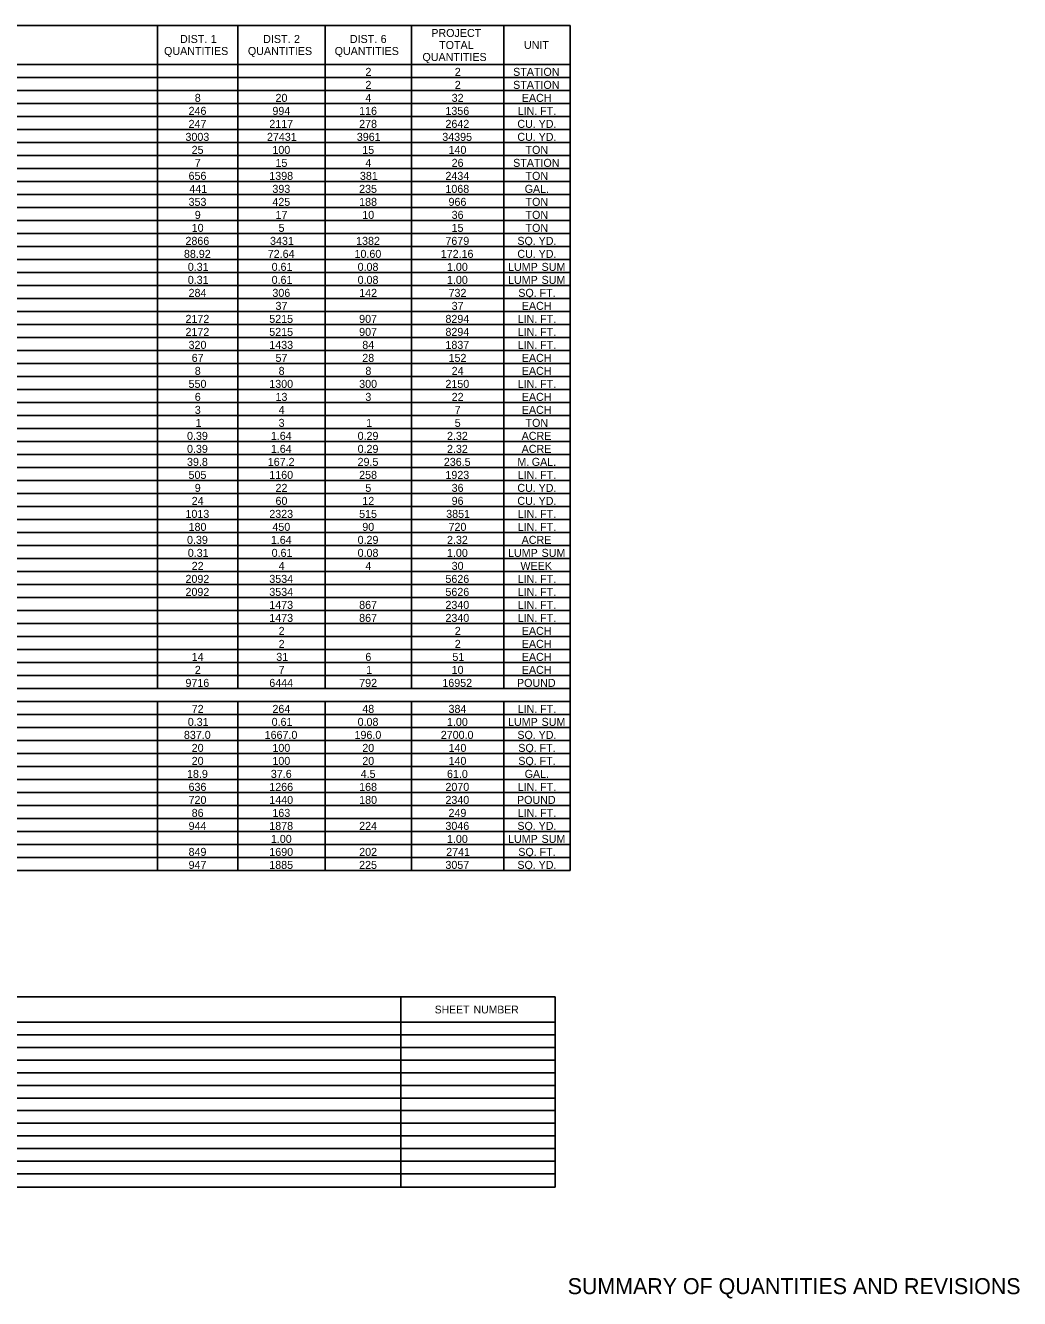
# Model space of a CAD drawing. Extents: x 542596 to 1930787, y -1948294 to 596640.
# Drawn here: x 545014 to 545760, y -1948294 to -1947339 of the extents above; entities that cross this region are included whole.
import ezdxf

# ---------------------------------------------------------------- set-up
doc = ezdxf.new("R2010")
doc.units = 0
doc.layers.add('Default', color=7, linetype='Continuous')
doc.layers.add('R_Border', color=7, linetype='Continuous')

msp = doc.modelspace()

# ---------------------------------------------------------------- linework, layer by layer
at = {"layer": 'Default'}
for p, q in [((544543.96, -1947339.48), (545422.43, -1947339.48)), ((545112.87, -1947836.73), (545112.87, -1947339.48)), ((545112.87, -1947700.23), (545112.87, -1947339.48)), ((545173.32, -1947836.73), (545173.32, -1947339.48)), ((545173.32, -1947368.73), (545173.32, -1947339.48)), ((545238.65, -1947836.73), (545238.65, -1947339.48)), ((545238.65, -1947368.73), (545238.65, -1947339.48)), ((545303.48, -1947836.73), (545303.48, -1947339.48)), ((545372.71, -1947836.73), (545372.71, -1947339.48)), ((545372.71, -1947836.73), (545372.71, -1947339.48)), ((545422.43, -1947973.23), (545422.43, -1947339.48)), ((544543.96, -1947368.73), (545422.43, -1947368.73)), ((544543.96, -1947378.48), (545422.43, -1947378.48)), ((544543.96, -1947388.23), (545422.43, -1947388.23)), ((544543.96, -1947397.98), (545422.43, -1947397.98)), ((544543.96, -1947407.73), (545422.43, -1947407.73)), ((544543.96, -1947417.48), (545422.43, -1947417.48)), ((544543.96, -1947427.23), (545422.43, -1947427.23)), ((544543.96, -1947436.98), (545422.43, -1947436.98)), ((544543.96, -1947446.73), (545422.43, -1947446.73)), ((544543.96, -1947456.48), (545422.43, -1947456.48)), ((544543.96, -1947466.23), (545422.43, -1947466.23)), ((544543.96, -1947475.98), (545422.43, -1947475.98)), ((544543.96, -1947485.73), (545422.43, -1947485.73)), ((544543.96, -1947495.48), (545422.43, -1947495.48)), ((544543.96, -1947505.23), (545422.43, -1947505.23)), ((544543.96, -1947514.98), (545422.43, -1947514.98)), ((544543.96, -1947524.73), (545422.43, -1947524.73)), ((544543.96, -1947534.48), (545422.43, -1947534.48)), ((544543.96, -1947544.23), (545422.43, -1947544.23)), ((544543.96, -1947553.98), (545422.43, -1947553.98)), ((544543.96, -1947563.73), (545422.43, -1947563.73)), ((544543.96, -1947573.48), (545422.43, -1947573.48)), ((544543.96, -1947583.23), (545422.43, -1947583.23)), ((544543.96, -1947592.98), (545422.43, -1947592.98)), ((544543.96, -1947602.73), (545422.43, -1947602.73)), ((544543.96, -1947612.48), (545422.43, -1947612.48)), ((544543.96, -1947622.23), (545422.43, -1947622.23)), ((544543.96, -1947631.98), (545422.43, -1947631.98)), ((544543.96, -1947641.73), (545422.43, -1947641.73)), ((544543.96, -1947651.48), (545422.43, -1947651.48)), ((544543.96, -1947661.23), (545422.43, -1947661.23)), ((544543.96, -1947670.98), (545422.43, -1947670.98)), ((544543.96, -1947680.73), (545422.43, -1947680.73)), ((544543.96, -1947690.48), (545422.43, -1947690.48)), ((544543.96, -1947700.23), (545422.43, -1947700.23)), ((544543.96, -1947709.98), (545422.43, -1947709.98)), ((545112.87, -1947836.73), (545112.87, -1947709.98)), ((545372.71, -1947709.98), (545422.43, -1947709.98)), ((544543.96, -1947719.73), (545422.43, -1947719.73)), ((544543.96, -1947729.48), (545422.43, -1947729.48)), ((544543.96, -1947739.23), (545422.43, -1947739.23)), ((544543.96, -1947748.98), (545422.43, -1947748.98)), ((545026.1, -1947748.98), (545112.87, -1947748.98)), ((545112.87, -1947748.98), (545422.43, -1947748.98)), ((544543.96, -1947758.73), (545422.43, -1947758.73)), ((544543.96, -1947768.48), (545422.43, -1947768.48)), ((544543.96, -1947778.23), (545422.43, -1947778.23)), ((544543.96, -1947787.98), (545422.43, -1947787.98)), ((544543.96, -1947797.73), (545422.43, -1947797.73)), ((544543.96, -1947807.48), (545422.43, -1947807.48)), ((544543.96, -1947817.23), (545422.43, -1947817.23)), ((544543.96, -1947826.98), (545422.43, -1947826.98)), ((544543.96, -1947836.73), (545422.43, -1947836.73)), ((544543.96, -1947836.73), (545422.43, -1947836.73)), ((544543.96, -1947846.48), (545422.43, -1947846.48)), ((544543.96, -1947846.48), (545422.43, -1947846.48)), ((545112.87, -1947973.23), (545112.87, -1947846.48)), ((545112.87, -1947973.23), (545112.87, -1947846.48)), ((545173.32, -1947973.23), (545173.32, -1947846.48)), ((545238.65, -1947973.23), (545238.65, -1947846.48)), ((545238.65, -1947973.23), (545238.65, -1947846.48)), ((545303.48, -1947973.23), (545303.48, -1947846.48)), ((545303.48, -1947973.23), (545303.48, -1947846.48)), ((545372.71, -1947973.23), (545372.71, -1947846.48)), ((545372.71, -1947973.23), (545372.71, -1947846.48)), ((544543.96, -1947856.23), (545422.43, -1947856.23)), ((544543.96, -1947865.98), (545422.43, -1947865.98)), ((544543.96, -1947875.73), (545422.43, -1947875.73)), ((544543.96, -1947885.48), (545422.43, -1947885.48)), ((544543.96, -1947895.23), (545422.43, -1947895.23)), ((545026.1, -1947895.23), (545112.87, -1947895.23)), ((545112.87, -1947895.23), (545238.65, -1947895.23)), ((545238.65, -1947895.23), (545372.71, -1947895.23)), ((545372.71, -1947895.23), (545422.43, -1947895.23)), ((544543.96, -1947904.98), (545422.43, -1947904.98)), ((544543.96, -1947914.73), (545422.43, -1947914.73)), ((544543.96, -1947924.48), (545422.43, -1947924.48)), ((544543.96, -1947934.23), (545422.43, -1947934.23)), ((544543.96, -1947943.98), (545422.43, -1947943.98)), ((545026.1, -1947943.98), (545112.87, -1947943.98)), ((545112.87, -1947943.98), (545238.65, -1947943.98)), ((545238.65, -1947943.98), (545372.71, -1947943.98)), ((545372.71, -1947943.98), (545422.43, -1947943.98)), ((544543.96, -1947953.73), (545422.43, -1947953.73)), ((544543.96, -1947963.48), (545422.43, -1947963.48)), ((544543.96, -1947973.23), (545422.43, -1947973.23)), ((544556.08, -1948068.01), (545411.29, -1948068.01)), ((545110.26, -1948068.01), (545411.29, -1948068.01)), ((545295.62, -1948086.97), (545295.62, -1948068.01)), ((545295.62, -1948210.7), (545295.62, -1948068.01)), ((545411.29, -1948210.7), (545411.29, -1948068.01)), ((544556.08, -1948086.97), (545411.29, -1948086.97)), ((545295.62, -1948086.97), (545411.29, -1948086.97)), ((544556.08, -1948096.45), (545411.29, -1948096.45)), ((544556.08, -1948105.93), (545411.29, -1948105.93)), ((544556.08, -1948115.42), (545411.29, -1948115.42)), ((544556.08, -1948124.9), (545411.29, -1948124.9)), ((544556.08, -1948134.38), (545411.29, -1948134.38)), ((544556.08, -1948143.86), (545411.29, -1948143.86)), ((544556.08, -1948153.34), (545411.29, -1948153.34)), ((544556.08, -1948162.82), (545411.29, -1948162.82)), ((544556.08, -1948172.3), (545411.29, -1948172.3)), ((544556.08, -1948181.78), (545411.29, -1948181.78)), ((544556.08, -1948191.27), (545411.29, -1948191.27)), ((544556.08, -1948200.75), (545411.29, -1948200.75)), ((544556.08, -1948210.7), (545411.29, -1948210.7))]:
    msp.add_line(p, q, dxfattribs=at)

# ---------------------------------------------------------------- texts
for s, height, p in [('PROJECT', 6, (545318.38, -1947348.11)), ('DIST.', 6, (545129.86, -1947352.61)), (' 1', 6, (545150.71, -1947352.61)), ('DIST.', 6, (545192.27, -1947352.61)), (' 2', 6, (545213.12, -1947352.61)), ('DIST.', 6, (545257.29, -1947352.61)), (' 6', 6, (545278.14, -1947352.61)), ('TOTAL', 6, (545324.25, -1947357.11)), ('UNIT', 6, (545387.88, -1947357.11)), ('QUANTITIES', 6, (545117.92, -1947361.61)), ('QUANTITIES', 6, (545180.8, -1947361.61)), ('QUANTITIES', 6, (545245.88, -1947361.61)), ('QUANTITIES', 6, (545311.75, -1947366.11)), ('2', 6, (545268.96, -1947377.28)), ('2', 6, (545335.99, -1947377.28)), ('STATION', 6, (545379.75, -1947377.28)), ('2', 6, (545268.96, -1947387.03)), ('2', 6, (545335.99, -1947387.03)), ('STATION', 6, (545379.75, -1947387.03)), ('8', 6, (545140.95, -1947396.78)), ('20', 6, (545201.52, -1947396.78)), ('4', 6, (545268.94, -1947396.78)), ('32', 6, (545333.66, -1947396.78)), ('EACH', 6, (545386.26, -1947396.78)), ('246', 6, (545136.3, -1947406.53)), ('994', 6, (545199.2, -1947406.53)), ('116', 6, (545264.26, -1947406.53)), ('1356', 6, (545328.97, -1947406.53)), ('LIN.', 6, (545383.17, -1947406.53)), (' FT.', 6, (545397.81, -1947406.53)), ('247', 6, (545136.3, -1947416.28)), ('2117', 6, (545196.85, -1947416.28)), ('278', 6, (545264.26, -1947416.28)), ('2642', 6, (545329, -1947416.28)), ('CU.', 6, (545382.93, -1947416.28)), (' YD.', 6, (545396.64, -1947416.28)), ('3003', 6, (545133.97, -1947426.03)), ('27431', 6, (545195.1, -1947426.03)), ('3961', 6, (545262.51, -1947426.03)), ('34395', 6, (545326.61, -1947426.03)), ('CU.', 6, (545382.93, -1947426.03)), (' YD.', 6, (545396.64, -1947426.03)), ('25', 6, (545138.6, -1947435.78)), ('100', 6, (545199.19, -1947435.78)), ('15', 6, (545266.57, -1947435.78)), ('140', 6, (545331.31, -1947435.78)), ('TON', 6, (545389.06, -1947435.78)), ('7', 6, (545140.96, -1947445.53)), ('15', 6, (545201.49, -1947445.53)), ('4', 6, (545268.94, -1947445.53)), ('26', 6, (545333.63, -1947445.53)), ('STATION', 6, (545379.75, -1947445.53)), ('656', 6, (545136.3, -1947455.28)), ('1398', 6, (545196.85, -1947455.28)), ('381', 6, (545264.84, -1947455.28)), ('2434', 6, (545328.98, -1947455.28)), ('TON', 6, (545389.06, -1947455.28)), ('441', 6, (545136.88, -1947465.03)), ('393', 6, (545199.18, -1947465.03)), ('235', 6, (545264.24, -1947465.03)), ('1068', 6, (545328.96, -1947465.03)), ('GAL.', 6, (545388.39, -1947465.03)), ('353', 6, (545136.3, -1947474.78)), ('425', 6, (545199.16, -1947474.78)), ('188', 6, (545264.26, -1947474.78)), ('966', 6, (545331.3, -1947474.78)), ('TON', 6, (545389.06, -1947474.78)), ('9', 6, (545140.95, -1947484.53)), ('17', 6, (545201.51, -1947484.53)), ('10', 6, (545266.61, -1947484.53)), ('36', 6, (545333.63, -1947484.53)), ('TON', 6, (545389.06, -1947484.53)), ('10', 6, (545138.64, -1947494.28)), ('5', 6, (545203.82, -1947494.28)), ('15', 6, (545333.6, -1947494.28)), ('TON', 6, (545389.06, -1947494.28)), ('2866', 6, (545133.97, -1947504.03)), ('3431', 6, (545197.43, -1947504.03)), ('1382', 6, (545261.97, -1947504.03)), ('7679', 6, (545328.96, -1947504.03)), ('SQ.', 6, (545382.93, -1947504.03)), (' YD.', 6, (545396.64, -1947504.03)), ('88.92', 6, (545132.83, -1947513.78)), ('72.64', 6, (545195.7, -1947513.78)), ('10.60', 6, (545260.78, -1947513.78)), ('172.16', 6, (545325.47, -1947513.78)), ('CU.', 6, (545382.93, -1947513.78)), (' YD.', 6, (545396.64, -1947513.78)), ('0.31', 6, (545135.71, -1947523.53)), ('0.61', 6, (545198.6, -1947523.53)), ('0.08', 6, (545263.1, -1947523.53)), ('1.00', 6, (545330.14, -1947523.53)), ('LUMP', 6, (545375.94, -1947523.53)), (' SUM', 6, (545398.87, -1947523.53)), ('0.31', 6, (545135.71, -1947533.28)), ('0.61', 6, (545198.6, -1947533.28)), ('0.08', 6, (545263.1, -1947533.28)), ('1.00', 6, (545330.14, -1947533.28)), ('LUMP', 6, (545375.94, -1947533.28)), (' SUM', 6, (545398.87, -1947533.28)), ('284', 6, (545136.31, -1947543.03)), ('306', 6, (545199.18, -1947543.03)), ('142', 6, (545264.3, -1947543.03)), ('732', 6, (545331.33, -1947543.03)), ('SQ.', 6, (545383.63, -1947543.03)), (' FT.', 6, (545397.34, -1947543.03)), ('37', 6, (545201.51, -1947552.78)), ('37', 6, (545333.63, -1947552.78)), ('EACH', 6, (545386.26, -1947552.78)), ('2172', 6, (545134, -1947562.53)), ('5215', 6, (545196.83, -1947562.53)), ('907', 6, (545264.26, -1947562.53)), ('8294', 6, (545328.98, -1947562.53)), ('LIN.', 6, (545383.17, -1947562.53)), (' FT.', 6, (545397.81, -1947562.53)), ('2172', 6, (545134, -1947572.28)), ('5215', 6, (545196.83, -1947572.28)), ('907', 6, (545264.26, -1947572.28)), ('8294', 6, (545328.98, -1947572.28)), ('LIN.', 6, (545383.17, -1947572.28)), (' FT.', 6, (545397.81, -1947572.28)), ('320', 6, (545136.31, -1947582.03)), ('1433', 6, (545196.85, -1947582.03)), ('84', 6, (545266.61, -1947582.03)), ('1837', 6, (545328.97, -1947582.03)), ('LIN.', 6, (545383.17, -1947582.03)), (' FT.', 6, (545397.81, -1947582.03)), ('67', 6, (545138.63, -1947591.78)), ('57', 6, (545201.51, -1947591.78)), ('28', 6, (545266.59, -1947591.78)), ('152', 6, (545331.33, -1947591.78)), ('EACH', 6, (545386.26, -1947591.78)), ('8', 6, (545140.95, -1947601.53)), ('8', 6, (545203.84, -1947601.53)), ('8', 6, (545268.92, -1947601.53)), ('24', 6, (545333.64, -1947601.53)), ('EACH', 6, (545386.26, -1947601.53)), ('550', 6, (545136.31, -1947611.28)), ('1300', 6, (545196.86, -1947611.28)), ('300', 6, (545264.28, -1947611.28)), ('2150', 6, (545328.98, -1947611.28)), ('LIN.', 6, (545383.17, -1947611.28)), (' FT.', 6, (545397.81, -1947611.28)), ('6', 6, (545140.96, -1947621.03)), ('13', 6, (545201.51, -1947621.03)), ('3', 6, (545268.92, -1947621.03)), ('22', 6, (545333.66, -1947621.03)), ('EACH', 6, (545386.26, -1947621.03)), ('3', 6, (545140.96, -1947630.78)), ('4', 6, (545203.86, -1947630.78)), ('7', 6, (545335.96, -1947630.78)), ('EACH', 6, (545386.26, -1947630.78)), ('1', 6, (545141.54, -1947640.53)), ('3', 6, (545203.84, -1947640.53)), ('1', 6, (545269.5, -1947640.53)), ('5', 6, (545335.93, -1947640.53)), ('TON', 6, (545389.06, -1947640.53)), ('0.39', 6, (545135.13, -1947650.28)), ('1.64', 6, (545198.03, -1947650.28)), ('0.29', 6, (545263.1, -1947650.28)), ('2.32', 6, (545330.16, -1947650.28)), ('ACRE', 6, (545386.15, -1947650.28)), ('0.39', 6, (545135.13, -1947660.03)), ('1.64', 6, (545198.03, -1947660.03)), ('0.29', 6, (545263.1, -1947660.03)), ('2.32', 6, (545330.16, -1947660.03)), ('ACRE', 6, (545386.15, -1947660.03)), ('39.8', 6, (545135.13, -1947669.78)), ('167.2', 6, (545195.72, -1947669.78)), ('29.5', 6, (545263.08, -1947669.78)), ('236.5', 6, (545327.78, -1947669.78)), ('M.', 6, (545382.93, -1947669.78)), (' GAL.', 6, (545391.51, -1947669.78)), ('505', 6, (545136.27, -1947679.53)), ('1160', 6, (545196.86, -1947679.53)), ('258', 6, (545264.26, -1947679.53)), ('1923', 6, (545328.97, -1947679.53)), ('LIN.', 6, (545383.17, -1947679.53)), (' FT.', 6, (545397.81, -1947679.53)), ('9', 6, (545140.95, -1947689.28)), ('22', 6, (545201.54, -1947689.28)), ('5', 6, (545268.9, -1947689.28)), ('36', 6, (545333.63, -1947689.28)), ('CU.', 6, (545382.93, -1947689.28)), (' YD.', 6, (545396.64, -1947689.28)), ('24', 6, (545138.64, -1947699.03)), ('60', 6, (545201.52, -1947699.03)), ('12', 6, (545266.63, -1947699.03)), ('96', 6, (545333.63, -1947699.03)), ('CU.', 6, (545382.93, -1947699.03)), (' YD.', 6, (545396.64, -1947699.03)), ('1013', 6, (545133.97, -1947708.78)), ('2323', 6, (545196.85, -1947708.78)), ('515', 6, (545264.24, -1947708.78)), ('3851', 6, (545329.55, -1947708.78)), ('LIN.', 6, (545383.17, -1947708.78)), (' FT.', 6, (545397.81, -1947708.78)), ('180', 6, (545136.31, -1947718.53)), ('450', 6, (545199.19, -1947718.53)), ('90', 6, (545266.61, -1947718.53)), ('720', 6, (545331.31, -1947718.53)), ('LIN.', 6, (545383.17, -1947718.53)), (' FT.', 6, (545397.81, -1947718.53)), ('0.39', 6, (545135.13, -1947728.28)), ('1.64', 6, (545198.03, -1947728.28)), ('0.29', 6, (545263.1, -1947728.28)), ('2.32', 6, (545330.16, -1947728.28)), ('ACRE', 6, (545386.15, -1947728.28)), ('0.31', 6, (545135.71, -1947738.03)), ('0.61', 6, (545198.6, -1947738.03)), ('0.08', 6, (545263.1, -1947738.03)), ('1.00', 6, (545330.14, -1947738.03)), ('LUMP', 6, (545375.94, -1947738.03)), (' SUM', 6, (545398.87, -1947738.03)), ('22', 6, (545138.66, -1947747.78)), ('4', 6, (545203.86, -1947747.78)), ('4', 6, (545268.94, -1947747.78)), ('30', 6, (545333.64, -1947747.78)), ('WEEK', 6, (545385.23, -1947747.78)), ('2092', 6, (545134, -1947757.53)), ('3534', 6, (545196.87, -1947757.53)), ('5626', 6, (545328.97, -1947757.53)), ('LIN.', 6, (545383.17, -1947757.53)), (' FT.', 6, (545397.81, -1947757.53)), ('2092', 6, (545134, -1947767.28)), ('3534', 6, (545196.87, -1947767.28)), ('5626', 6, (545328.97, -1947767.28)), ('LIN.', 6, (545383.17, -1947767.28)), (' FT.', 6, (545397.81, -1947767.28)), ('1473', 6, (545196.85, -1947777.03)), ('867', 6, (545264.26, -1947777.03)), ('2340', 6, (545328.98, -1947777.03)), ('LIN.', 6, (545383.17, -1947777.03)), (' FT.', 6, (545397.81, -1947777.03)), ('1473', 6, (545196.85, -1947786.78)), ('867', 6, (545264.26, -1947786.78)), ('2340', 6, (545328.98, -1947786.78)), ('LIN.', 6, (545383.17, -1947786.78)), (' FT.', 6, (545397.81, -1947786.78)), ('2', 6, (545203.87, -1947796.53)), ('2', 6, (545335.99, -1947796.53)), ('EACH', 6, (545386.26, -1947796.53)), ('2', 6, (545203.87, -1947806.28)), ('2', 6, (545335.99, -1947806.28)), ('EACH', 6, (545386.26, -1947806.28)), ('14', 6, (545138.64, -1947816.03)), ('31', 6, (545202.09, -1947816.03)), ('6', 6, (545268.92, -1947816.03)), ('51', 6, (545334.21, -1947816.03)), ('EACH', 6, (545386.26, -1947816.03)), ('2', 6, (545140.99, -1947825.78)), ('7', 6, (545203.84, -1947825.78)), ('1', 6, (545269.5, -1947825.78)), ('10', 6, (545333.64, -1947825.78)), ('EACH', 6, (545386.26, -1947825.78)), ('9716', 6, (545133.97, -1947835.53)), ('6444', 6, (545196.87, -1947835.53)), ('792', 6, (545264.3, -1947835.53)), ('16952', 6, (545326.67, -1947835.53)), ('POUND', 6, (545382.65, -1947835.53)), ('72', 6, (545138.66, -1947855.03)), ('264', 6, (545199.2, -1947855.03)), ('48', 6, (545266.59, -1947855.03)), ('384', 6, (545331.31, -1947855.03)), ('LIN.', 6, (545383.17, -1947855.03)), (' FT.', 6, (545397.81, -1947855.03)), ('0.31', 6, (545135.71, -1947864.78)), ('0.61', 6, (545198.6, -1947864.78)), ('0.08', 6, (545263.1, -1947864.78)), ('1.00', 6, (545330.14, -1947864.78)), ('LUMP', 6, (545375.94, -1947864.78)), (' SUM', 6, (545398.87, -1947864.78)), ('837.0', 6, (545132.81, -1947874.53)), ('1667.0', 6, (545193.37, -1947874.53)), ('196.0', 6, (545260.78, -1947874.53)), ('2700.0', 6, (545325.48, -1947874.53)), ('SQ.', 6, (545382.93, -1947874.53)), (' YD.', 6, (545396.64, -1947874.53)), ('20', 6, (545138.64, -1947884.28)), ('100', 6, (545199.19, -1947884.28)), ('20', 6, (545266.61, -1947884.28)), ('140', 6, (545331.31, -1947884.28)), ('SQ.', 6, (545383.63, -1947884.28)), (' FT.', 6, (545397.34, -1947884.28)), ('20', 6, (545138.64, -1947894.03)), ('100', 6, (545199.19, -1947894.03)), ('20', 6, (545266.61, -1947894.03)), ('140', 6, (545331.31, -1947894.03)), ('SQ.', 6, (545383.63, -1947894.03)), (' FT.', 6, (545397.34, -1947894.03)), ('18.9', 6, (545135.13, -1947903.78)), ('37.6', 6, (545198.02, -1947903.78)), ('4.5', 6, (545265.41, -1947903.78)), ('61.0', 6, (545330.14, -1947903.78)), ('GAL.', 6, (545388.39, -1947903.78)), ('636', 6, (545136.3, -1947913.53)), ('1266', 6, (545196.85, -1947913.53)), ('168', 6, (545264.26, -1947913.53)), ('2070', 6, (545328.98, -1947913.53)), ('LIN.', 6, (545383.17, -1947913.53)), (' FT.', 6, (545397.81, -1947913.53)), ('720', 6, (545136.31, -1947923.28)), ('1440', 6, (545196.86, -1947923.28)), ('180', 6, (545264.28, -1947923.28)), ('2340', 6, (545328.98, -1947923.28)), ('POUND', 6, (545382.65, -1947923.28)), ('86', 6, (545138.63, -1947933.03)), ('163', 6, (545199.18, -1947933.03)), ('249', 6, (545331.29, -1947933.03)), ('LIN.', 6, (545383.17, -1947933.03)), (' FT.', 6, (545397.81, -1947933.03)), ('944', 6, (545136.31, -1947942.78)), ('1878', 6, (545196.85, -1947942.78)), ('224', 6, (545264.28, -1947942.78)), ('3046', 6, (545328.97, -1947942.78)), ('SQ.', 6, (545382.93, -1947942.78)), (' YD.', 6, (545396.64, -1947942.78)), ('1.00', 6, (545198.03, -1947952.53)), ('1.00', 6, (545330.14, -1947952.53)), ('LUMP', 6, (545375.94, -1947952.53)), (' SUM', 6, (545398.87, -1947952.53)), ('849', 6, (545136.29, -1947962.28)), ('1690', 6, (545196.86, -1947962.28)), ('202', 6, (545264.3, -1947962.28)), ('2741', 6, (545329.55, -1947962.28)), ('SQ.', 6, (545383.63, -1947962.28)), (' FT.', 6, (545397.34, -1947962.28)), ('947', 6, (545136.3, -1947972.03)), ('1885', 6, (545196.83, -1947972.03)), ('225', 6, (545264.24, -1947972.03)), ('3057', 6, (545328.97, -1947972.03)), ('SQ.', 6, (545382.93, -1947972.03)), (' YD.', 6, (545396.64, -1947972.03)), ('SHEET', 5.835, (545320.94, -1948080.41)), (' NUMBER', 5.835, (545347.96, -1948080.41))]:
    msp.add_text(s, height=height, dxfattribs=at).set_placement(p)
at = {"layer": 'R_Border'}
msp.add_text('SUMMARY OF QUANTITIES AND REVISIONS', height=12, rotation=360, dxfattribs=at).set_placement((545420.66, -1948290.95))

doc.saveas('drawing.dxf')
